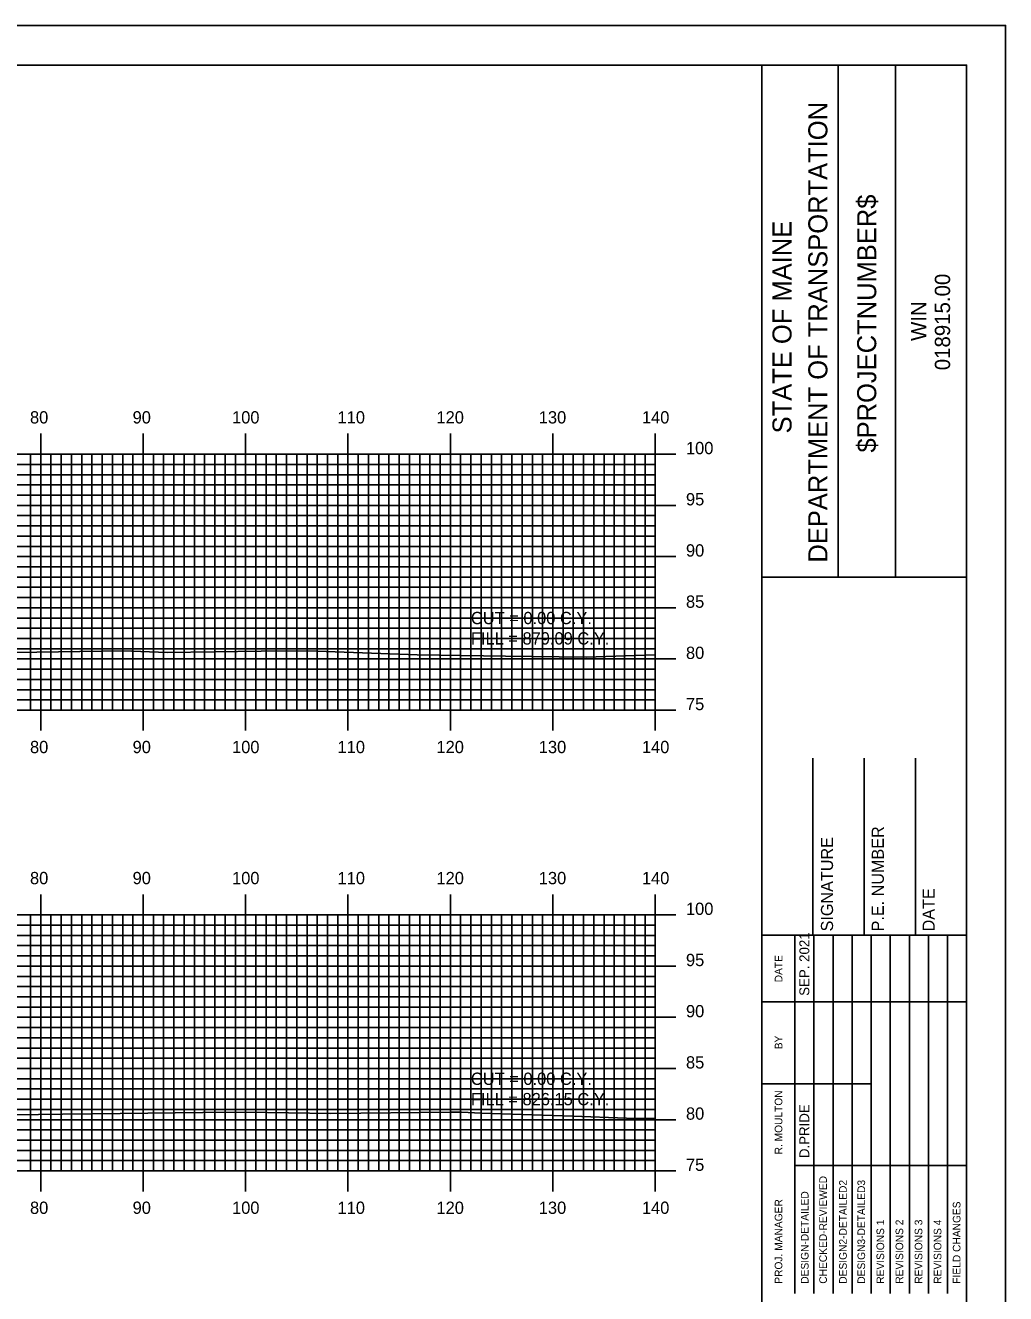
# Model space of a CAD drawing. Extents: x 856323 to 856666, y 364765 to 364985.
# Drawn here: x 856567.3 to 856663, y 364861.3 to 364985.2 of the extents above; entities that cross this region are included whole.
import ezdxf

# ---------------------------------------------------------------- set-up
doc = ezdxf.new("R2010")
doc.units = 0
for name, color, linetype in [('BORDER', 7, 'Continuous'), ('D_Text_Standard', 7, 'Continuous'), ('H_V ANNOTATION', 7, 'Continuous'), ('MAJOR', 7, 'Continuous'), ('MINOR', 7, 'Continuous'), ('PLOT BOUNDARY', 7, 'Continuous'), ('S_Roadway_Centerline', 7, 'Continuous')]:
    doc.layers.add(name, color=color, linetype=linetype)

msp = doc.modelspace()

# ---------------------------------------------------------------- linework, layer by layer
at = {"layer": 'BORDER'}
for p, q in [((856639.17, 364771.3), (856639.17, 364981.3)), ((856646.63, 364931.3), (856646.63, 364981.3)), ((856652.22, 364931.3), (856652.22, 364981.3)), ((856639.17, 364931.29), (856659.17, 364931.29)), ((856644.17, 364896.31), (856644.17, 364913.6)), ((856649.17, 364896.31), (856649.17, 364913.6)), ((856654.17, 364896.31), (856654.17, 364913.6)), ((856639.17, 364896.31), (856659.17, 364896.31))]:
    msp.add_line(p, q, dxfattribs=at)
msp.add_lwpolyline([(856339.17, 364771.3), (856659.17, 364771.3), (856659.17, 364981.3), (856339.17, 364981.3)], close=True, dxfattribs=at)
for points in [[(856642.4, 364889.81), (856642.4, 364896.31)], [(856644.26, 364861.31), (856644.26, 364896.31)], [(856646.13, 364896.31), (856646.13, 364861.31)], [(856647.99, 364861.31), (856647.99, 364896.31)], [(856649.85, 364861.31), (856649.85, 364896.31)], [(856651.72, 364861.31), (856651.72, 364896.31)], [(856653.58, 364861.31), (856653.58, 364896.31)], [(856655.44, 364861.31), (856655.44, 364896.31)], [(856657.31, 364861.31), (856657.31, 364896.31)], [(856642.4, 364861.31), (856642.4, 364894.9)], [(856639.17, 364889.81), (856659.17, 364889.81)], [(856639.17, 364881.81), (856642.4, 364881.81)], [(856642.4, 364881.81), (856649.85, 364881.81)], [(856642.4, 364873.81), (856659.17, 364873.81)]]:
    msp.add_lwpolyline(points, dxfattribs=at)
at = {"layer": 'MAJOR'}
for p, q in [((856568.77, 364945.31), (856568.77, 364943.3)), ((856578.77, 364945.31), (856578.77, 364943.3)), ((856588.77, 364945.31), (856588.77, 364943.3)), ((856598.77, 364945.31), (856598.77, 364943.3)), ((856608.77, 364945.31), (856608.77, 364943.3)), ((856618.77, 364945.31), (856618.77, 364943.3)), ((856628.77, 364945.31), (856628.77, 364943.3)), ((856348.77, 364943.3), (856628.77, 364943.3)), ((856348.77, 364943.3), (856628.77, 364943.3)), ((856568.77, 364918.3), (856568.77, 364943.3)), ((856578.77, 364918.3), (856578.77, 364943.3)), ((856588.77, 364918.3), (856588.77, 364943.3)), ((856598.77, 364918.3), (856598.77, 364943.3)), ((856608.77, 364918.3), (856608.77, 364943.3)), ((856618.77, 364918.3), (856618.77, 364943.3)), ((856630.77, 364943.3), (856626.76, 364943.3)), ((856628.77, 364918.3), (856628.77, 364943.3)), ((856628.77, 364918.3), (856628.77, 364943.3)), ((856348.77, 364938.3), (856628.77, 364938.3)), ((856630.77, 364938.3), (856626.76, 364938.3)), ((856348.77, 364933.3), (856628.77, 364933.3)), ((856630.77, 364933.3), (856626.76, 364933.3)), ((856348.77, 364928.3), (856628.77, 364928.3)), ((856630.77, 364928.3), (856626.76, 364928.3)), ((856348.77, 364923.3), (856628.77, 364923.3)), ((856630.77, 364923.3), (856626.76, 364923.3)), ((856348.77, 364918.3), (856628.77, 364918.3)), ((856348.77, 364918.3), (856628.77, 364918.3)), ((856568.77, 364916.3), (856568.77, 364918.3)), ((856578.77, 364916.3), (856578.77, 364918.3)), ((856588.77, 364916.3), (856588.77, 364918.3)), ((856598.77, 364916.3), (856598.77, 364918.3)), ((856608.77, 364916.3), (856608.77, 364918.3)), ((856618.77, 364916.3), (856618.77, 364918.3)), ((856630.77, 364918.3), (856626.76, 364918.3)), ((856628.77, 364916.3), (856628.77, 364918.3)), ((856568.77, 364900.31), (856568.77, 364898.3)), ((856578.77, 364900.31), (856578.77, 364898.3)), ((856588.77, 364900.31), (856588.77, 364898.3)), ((856598.77, 364900.31), (856598.77, 364898.3)), ((856608.77, 364900.31), (856608.77, 364898.3)), ((856618.77, 364900.31), (856618.77, 364898.3)), ((856628.77, 364900.31), (856628.77, 364898.3)), ((856348.77, 364898.3), (856628.77, 364898.3)), ((856348.77, 364898.3), (856628.77, 364898.3)), ((856568.77, 364873.3), (856568.77, 364898.3)), ((856578.77, 364873.3), (856578.77, 364898.3)), ((856588.77, 364873.3), (856588.77, 364898.3)), ((856598.77, 364873.3), (856598.77, 364898.3)), ((856608.77, 364873.3), (856608.77, 364898.3)), ((856618.77, 364873.3), (856618.77, 364898.3)), ((856630.77, 364898.3), (856626.76, 364898.3)), ((856628.77, 364873.3), (856628.77, 364898.3)), ((856628.77, 364873.3), (856628.77, 364898.3)), ((856348.77, 364893.3), (856628.77, 364893.3)), ((856630.77, 364893.3), (856626.76, 364893.3)), ((856348.77, 364888.3), (856628.77, 364888.3)), ((856630.77, 364888.3), (856626.76, 364888.3)), ((856348.77, 364883.3), (856628.77, 364883.3)), ((856630.77, 364883.3), (856626.76, 364883.3)), ((856348.77, 364878.3), (856628.77, 364878.3)), ((856630.77, 364878.3), (856626.76, 364878.3)), ((856348.77, 364873.3), (856628.77, 364873.3)), ((856348.77, 364873.3), (856628.77, 364873.3)), ((856568.77, 364871.3), (856568.77, 364873.3)), ((856578.77, 364871.3), (856578.77, 364873.3)), ((856588.77, 364871.3), (856588.77, 364873.3)), ((856598.77, 364871.3), (856598.77, 364873.3)), ((856608.77, 364871.3), (856608.77, 364873.3)), ((856618.77, 364871.3), (856618.77, 364873.3)), ((856630.77, 364873.3), (856626.76, 364873.3)), ((856628.77, 364871.3), (856628.77, 364873.3))]:
    msp.add_line(p, q, dxfattribs=at)
at = {"layer": 'MINOR'}
for p, q in [((856567.77, 364918.3), (856567.77, 364943.3)), ((856569.77, 364918.3), (856569.77, 364943.3)), ((856570.77, 364918.3), (856570.77, 364943.3)), ((856571.77, 364918.3), (856571.77, 364943.3)), ((856572.77, 364918.3), (856572.77, 364943.3)), ((856573.77, 364918.3), (856573.77, 364943.3)), ((856574.77, 364918.3), (856574.77, 364943.3)), ((856575.77, 364918.3), (856575.77, 364943.3)), ((856576.77, 364918.3), (856576.77, 364943.3)), ((856577.77, 364918.3), (856577.77, 364943.3)), ((856579.77, 364918.3), (856579.77, 364943.3)), ((856580.77, 364918.3), (856580.77, 364943.3)), ((856581.77, 364918.3), (856581.77, 364943.3)), ((856582.77, 364918.3), (856582.77, 364943.3)), ((856583.77, 364918.3), (856583.77, 364943.3)), ((856584.77, 364918.3), (856584.77, 364943.3)), ((856585.77, 364918.3), (856585.77, 364943.3)), ((856586.77, 364918.3), (856586.77, 364943.3)), ((856587.77, 364918.3), (856587.77, 364943.3)), ((856589.77, 364918.3), (856589.77, 364943.3)), ((856590.77, 364918.3), (856590.77, 364943.3)), ((856591.77, 364918.3), (856591.77, 364943.3)), ((856592.77, 364918.3), (856592.77, 364943.3)), ((856593.77, 364918.3), (856593.77, 364943.3)), ((856594.77, 364918.3), (856594.77, 364943.3)), ((856595.77, 364918.3), (856595.77, 364943.3)), ((856596.77, 364918.3), (856596.77, 364943.3)), ((856597.77, 364918.3), (856597.77, 364943.3)), ((856599.77, 364918.3), (856599.77, 364943.3)), ((856600.77, 364918.3), (856600.77, 364943.3)), ((856601.77, 364918.3), (856601.77, 364943.3)), ((856602.77, 364918.3), (856602.77, 364943.3)), ((856603.77, 364918.3), (856603.77, 364943.3)), ((856604.77, 364918.3), (856604.77, 364943.3)), ((856605.77, 364918.3), (856605.77, 364943.3)), ((856606.77, 364918.3), (856606.77, 364943.3)), ((856607.77, 364918.3), (856607.77, 364943.3)), ((856609.77, 364918.3), (856609.77, 364943.3)), ((856610.77, 364918.3), (856610.77, 364943.3)), ((856611.77, 364918.3), (856611.77, 364943.3)), ((856612.77, 364918.3), (856612.77, 364943.3)), ((856613.77, 364918.3), (856613.77, 364943.3)), ((856614.77, 364918.3), (856614.77, 364943.3)), ((856615.77, 364918.3), (856615.77, 364943.3)), ((856616.77, 364918.3), (856616.77, 364943.3)), ((856617.77, 364918.3), (856617.77, 364943.3)), ((856619.77, 364918.3), (856619.77, 364943.3)), ((856620.77, 364918.3), (856620.77, 364943.3)), ((856621.77, 364918.3), (856621.77, 364943.3)), ((856622.77, 364918.3), (856622.77, 364943.3)), ((856623.77, 364918.3), (856623.77, 364943.3)), ((856624.77, 364918.3), (856624.77, 364943.3)), ((856625.77, 364918.3), (856625.77, 364943.3)), ((856626.77, 364918.3), (856626.77, 364943.3)), ((856627.77, 364918.3), (856627.77, 364943.3)), ((856348.77, 364942.3), (856628.77, 364942.3)), ((856628.77, 364942.3), (856626.76, 364942.3)), ((856348.77, 364941.3), (856628.77, 364941.3)), ((856628.77, 364941.3), (856626.76, 364941.3)), ((856348.77, 364940.3), (856628.77, 364940.3)), ((856348.77, 364939.3), (856628.77, 364939.3)), ((856628.77, 364940.3), (856626.76, 364940.3)), ((856628.77, 364939.3), (856626.76, 364939.3)), ((856348.77, 364937.3), (856628.77, 364937.3)), ((856628.77, 364937.3), (856626.76, 364937.3)), ((856348.77, 364936.3), (856628.77, 364936.3)), ((856628.77, 364936.3), (856626.76, 364936.3)), ((856348.77, 364935.3), (856628.77, 364935.3)), ((856348.77, 364934.3), (856628.77, 364934.3)), ((856628.77, 364935.3), (856626.76, 364935.3)), ((856628.77, 364934.3), (856626.76, 364934.3)), ((856348.77, 364932.3), (856628.77, 364932.3)), ((856628.77, 364932.3), (856626.76, 364932.3)), ((856348.77, 364931.3), (856628.77, 364931.3)), ((856628.77, 364931.3), (856626.76, 364931.3)), ((856348.77, 364930.3), (856628.77, 364930.3)), ((856628.77, 364930.3), (856626.76, 364930.3)), ((856348.77, 364929.3), (856628.77, 364929.3)), ((856628.77, 364929.3), (856626.76, 364929.3)), ((856348.77, 364927.3), (856628.77, 364927.3)), ((856628.77, 364927.3), (856626.76, 364927.3)), ((856348.77, 364926.3), (856628.77, 364926.3)), ((856628.77, 364926.3), (856626.76, 364926.3)), ((856348.77, 364925.3), (856628.77, 364925.3)), ((856628.77, 364925.3), (856626.76, 364925.3)), ((856348.77, 364924.3), (856628.77, 364924.3)), ((856628.77, 364924.3), (856626.76, 364924.3)), ((856348.77, 364922.3), (856628.77, 364922.3)), ((856628.77, 364922.3), (856626.76, 364922.3)), ((856348.77, 364921.3), (856628.77, 364921.3)), ((856628.77, 364921.3), (856626.76, 364921.3)), ((856348.77, 364920.3), (856628.77, 364920.3)), ((856628.77, 364920.3), (856626.76, 364920.3)), ((856348.77, 364919.3), (856628.77, 364919.3)), ((856628.77, 364919.3), (856626.76, 364919.3)), ((856348.77, 364897.3), (856628.77, 364897.3)), ((856567.77, 364873.3), (856567.77, 364898.3)), ((856569.77, 364873.3), (856569.77, 364898.3)), ((856570.77, 364873.3), (856570.77, 364898.3)), ((856571.77, 364873.3), (856571.77, 364898.3)), ((856572.77, 364873.3), (856572.77, 364898.3)), ((856573.77, 364873.3), (856573.77, 364898.3)), ((856574.77, 364873.3), (856574.77, 364898.3)), ((856575.77, 364873.3), (856575.77, 364898.3)), ((856576.77, 364873.3), (856576.77, 364898.3)), ((856577.77, 364873.3), (856577.77, 364898.3)), ((856579.77, 364873.3), (856579.77, 364898.3)), ((856580.77, 364873.3), (856580.77, 364898.3)), ((856581.77, 364873.3), (856581.77, 364898.3)), ((856582.77, 364873.3), (856582.77, 364898.3)), ((856583.77, 364873.3), (856583.77, 364898.3)), ((856584.77, 364873.3), (856584.77, 364898.3)), ((856585.77, 364873.3), (856585.77, 364898.3)), ((856586.77, 364873.3), (856586.77, 364898.3)), ((856587.77, 364873.3), (856587.77, 364898.3)), ((856589.77, 364873.3), (856589.77, 364898.3)), ((856590.77, 364873.3), (856590.77, 364898.3)), ((856591.77, 364873.3), (856591.77, 364898.3)), ((856592.77, 364873.3), (856592.77, 364898.3)), ((856593.77, 364873.3), (856593.77, 364898.3)), ((856594.77, 364873.3), (856594.77, 364898.3)), ((856595.77, 364873.3), (856595.77, 364898.3)), ((856596.77, 364873.3), (856596.77, 364898.3)), ((856597.77, 364873.3), (856597.77, 364898.3)), ((856599.77, 364873.3), (856599.77, 364898.3)), ((856600.77, 364873.3), (856600.77, 364898.3)), ((856601.77, 364873.3), (856601.77, 364898.3)), ((856602.77, 364873.3), (856602.77, 364898.3)), ((856603.77, 364873.3), (856603.77, 364898.3)), ((856604.77, 364873.3), (856604.77, 364898.3)), ((856605.77, 364873.3), (856605.77, 364898.3)), ((856606.77, 364873.3), (856606.77, 364898.3)), ((856607.77, 364873.3), (856607.77, 364898.3)), ((856609.77, 364873.3), (856609.77, 364898.3)), ((856610.77, 364873.3), (856610.77, 364898.3)), ((856611.77, 364873.3), (856611.77, 364898.3)), ((856612.77, 364873.3), (856612.77, 364898.3)), ((856613.77, 364873.3), (856613.77, 364898.3)), ((856614.77, 364873.3), (856614.77, 364898.3)), ((856615.77, 364873.3), (856615.77, 364898.3)), ((856616.77, 364873.3), (856616.77, 364898.3)), ((856617.77, 364873.3), (856617.77, 364898.3)), ((856619.77, 364873.3), (856619.77, 364898.3)), ((856620.77, 364873.3), (856620.77, 364898.3)), ((856621.77, 364873.3), (856621.77, 364898.3)), ((856622.77, 364873.3), (856622.77, 364898.3)), ((856623.77, 364873.3), (856623.77, 364898.3)), ((856624.77, 364873.3), (856624.77, 364898.3)), ((856625.77, 364873.3), (856625.77, 364898.3)), ((856628.77, 364897.3), (856626.76, 364897.3)), ((856626.77, 364873.3), (856626.77, 364898.3)), ((856627.77, 364873.3), (856627.77, 364898.3)), ((856348.77, 364896.3), (856628.77, 364896.3)), ((856628.77, 364896.3), (856626.76, 364896.3)), ((856348.77, 364895.3), (856628.77, 364895.3)), ((856628.77, 364895.3), (856626.76, 364895.3)), ((856348.77, 364894.3), (856628.77, 364894.3)), ((856628.77, 364894.3), (856626.76, 364894.3)), ((856348.77, 364892.3), (856628.77, 364892.3)), ((856628.77, 364892.3), (856626.76, 364892.3)), ((856348.77, 364891.3), (856628.77, 364891.3)), ((856628.77, 364891.3), (856626.76, 364891.3)), ((856348.77, 364890.3), (856628.77, 364890.3)), ((856628.77, 364890.3), (856626.76, 364890.3)), ((856348.77, 364889.3), (856628.77, 364889.3)), ((856628.77, 364889.3), (856626.76, 364889.3)), ((856348.77, 364887.3), (856628.77, 364887.3)), ((856628.77, 364887.3), (856626.76, 364887.3)), ((856348.77, 364886.3), (856628.77, 364886.3)), ((856628.77, 364886.3), (856626.76, 364886.3)), ((856348.77, 364885.3), (856628.77, 364885.3)), ((856628.77, 364885.3), (856626.76, 364885.3)), ((856348.77, 364884.3), (856628.77, 364884.3)), ((856628.77, 364884.3), (856626.76, 364884.3)), ((856348.77, 364882.3), (856628.77, 364882.3)), ((856628.77, 364882.3), (856626.76, 364882.3)), ((856348.77, 364881.3), (856628.77, 364881.3)), ((856628.77, 364881.3), (856626.76, 364881.3)), ((856348.77, 364880.3), (856628.77, 364880.3)), ((856628.77, 364880.3), (856626.76, 364880.3)), ((856348.77, 364879.3), (856628.77, 364879.3)), ((856628.77, 364879.3), (856626.76, 364879.3)), ((856348.77, 364877.3), (856628.77, 364877.3)), ((856628.77, 364877.3), (856626.76, 364877.3)), ((856348.77, 364876.3), (856628.77, 364876.3)), ((856628.77, 364876.3), (856626.76, 364876.3)), ((856348.77, 364875.3), (856628.77, 364875.3)), ((856628.77, 364875.3), (856626.76, 364875.3)), ((856348.77, 364874.3), (856628.77, 364874.3)), ((856628.77, 364874.3), (856626.76, 364874.3))]:
    msp.add_line(p, q, dxfattribs=at)
at = {"layer": 'PLOT BOUNDARY'}
msp.add_lwpolyline([(856322.98, 364765.18), (856662.98, 364765.18), (856662.98, 364985.18), (856322.98, 364985.18)], close=True, dxfattribs=at)
at = {"layer": 'S_Roadway_Centerline'}
for points in [[(856469.99, 364924.48), (856481.66, 364924.38), (856483.59, 364924.39), (856484.17, 364924.38), (856486.38, 364924.39), (856503.32, 364924.46), (856516.92, 364924.34), (856521.76, 364924.3), (856531.69, 364924.06), (856540.75, 364923.82), (856544.17, 364923.83), (856550.39, 364923.82), (856555.71, 364923.79), (856559.44, 364923.93), (856566.27, 364923.94), (856576.82, 364924.1), (856581.11, 364923.92), (856590.28, 364924.07), (856594.86, 364924.09), (856605.52, 364923.7), (856614.14, 364923.57), (856622.01, 364923.48), (856628.77, 364923.69)], [(856563.84, 364878.75), (856570.89, 364878.85), (856576.53, 364878.9), (856584.58, 364878.99), (856588.83, 364879.04), (856597.1, 364878.92), (856608.79, 364879.05), (856609.84, 364879.03), (856611.76, 364878.94), (856619.83, 364878.68), (856626.83, 364878.43), (856628.77, 364878.43)]]:
    msp.add_lwpolyline(points, dxfattribs=at)

# ---------------------------------------------------------------- texts
at = {"layer": 'BORDER'}
for s, height, p in [('DEPARTMENT OF TRANSPORTATION', 1.8635, (856645.58, 364932.71)), ('$PROJECTNUMBER$', 1.8635, (856650.35, 364943.46)), ('STATE OF MAINE', 1.8635, (856642.08, 364945.33)), ('018915.00', 1.491, (856657.56, 364951.5)), ('WIN', 1.491, (856655.24, 364954.36)), ('SIGNATURE', 1.181, (856646.13, 364896.69)), ('P.E. NUMBER', 1.1811, (856651.09, 364896.69)), ('DATE', 1.181, (856656.05, 364896.69)), ('SEP. 2021', 0.969, (856643.81, 364890.4)), ('DATE', 0.743, (856641.18, 364891.72)), ('BY', 0.743, (856641.18, 364885.18)), ('R. MOULTON', 0.745, (856641.18, 364874.91)), ('D.PRIDE', 0.969, (856643.81, 364874.55)), ('CHECKED-REVIEWED', 0.7455, (856645.53, 364862.28)), ('DESIGN2-DETAILED2', 0.7455, (856647.47, 364862.28)), ('DESIGN3-DETAILED3', 0.7455, (856649.26, 364862.28)), ('DESIGN-DETAILED', 0.7455, (856643.74, 364862.28)), ('PROJ. MANAGER', 0.7455, (856641.18, 364862.28)), ('FIELD CHANGES', 0.7455, (856658.57, 364862.28)), ('REVISIONS 1', 0.7455, (856651.12, 364862.28)), ('REVISIONS 2', 0.7455, (856652.98, 364862.28)), ('REVISIONS 3', 0.7455, (856654.85, 364862.28)), ('REVISIONS 4', 0.7455, (856656.71, 364862.28))]:
    msp.add_text(s, height=height, rotation=90, dxfattribs=at).set_placement(p)
at = {"layer": 'D_Text_Standard'}
for s, p in [('CUT = 0.00 C.Y.', (856610.77, 364926.7)), ('FILL = 879.09 C.Y.', (856610.77, 364924.71)), ('CUT = 0.00 C.Y.', (856610.77, 364881.7)), ('FILL = 826.15 C.Y.', (856610.77, 364879.71))]:
    msp.add_text(s, height=1.2, dxfattribs=at).set_placement(p)
at = {"layer": 'H_V ANNOTATION'}
for s, p in [('80', (856567.72, 364946.3)), ('90', (856577.74, 364946.3)), ('100', (856587.45, 364946.3)), ('110', (856597.75, 364946.3)), ('120', (856607.41, 364946.3)), ('130', (856617.4, 364946.3)), ('140', (856627.47, 364946.3)), ('100', (856631.77, 364943.3)), ('95', (856631.77, 364938.3)), ('90', (856631.77, 364933.3)), ('85', (856631.77, 364928.3)), ('80', (856631.77, 364923.3)), ('75', (856631.77, 364918.3)), ('80', (856567.72, 364914.1)), ('90', (856577.74, 364914.1)), ('100', (856587.45, 364914.1)), ('110', (856597.75, 364914.1)), ('120', (856607.41, 364914.1)), ('130', (856617.4, 364914.1)), ('140', (856627.47, 364914.1)), ('80', (856567.72, 364901.3)), ('90', (856577.74, 364901.3)), ('100', (856587.45, 364901.3)), ('110', (856597.75, 364901.3)), ('120', (856607.41, 364901.3)), ('130', (856617.4, 364901.3)), ('140', (856627.47, 364901.3)), ('100', (856631.77, 364898.3)), ('95', (856631.77, 364893.3)), ('90', (856631.77, 364888.3)), ('85', (856631.77, 364883.3)), ('80', (856631.77, 364878.3)), ('75', (856631.77, 364873.3)), ('80', (856567.72, 364869.1)), ('90', (856577.74, 364869.1)), ('100', (856587.45, 364869.1)), ('110', (856597.75, 364869.1)), ('120', (856607.41, 364869.1)), ('130', (856617.4, 364869.1)), ('140', (856627.47, 364869.1))]:
    msp.add_text(s, height=1.2, dxfattribs=at).set_placement(p)

doc.saveas('drawing.dxf')
